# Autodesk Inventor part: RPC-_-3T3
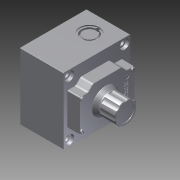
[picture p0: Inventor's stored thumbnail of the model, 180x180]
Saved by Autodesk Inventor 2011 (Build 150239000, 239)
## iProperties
Created: 2012-01
Part Number: RPC-_-3T3
Document SubType Name: Modeling
Designer: khramov
Density: 1 g/cm^3
Author: khramov
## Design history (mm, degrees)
derived "RPC_3T3_43.iam"
node "Твердое тело1"
node "0113965.ipt:1"
node "0113007.ipt:1"
node "0110595.ipt:1"
sketch "0570194.ipt:1"
sketch "0113106.ipt:1"
sketch "0550326.ipt:1"
sketch "0550326.ipt:2"
sketch "0113087_.ipt:1"
sketch "0113087_.ipt:2"
